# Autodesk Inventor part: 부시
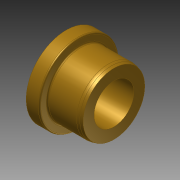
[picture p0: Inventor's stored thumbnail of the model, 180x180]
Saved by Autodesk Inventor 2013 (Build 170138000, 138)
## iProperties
Created: 2016-05
Part Number: 부시
Document SubType Name: Modeling
Designer: mduedu
Density: 7.86 g/cm^3
Material: 강철, 연강
Author: mduedu
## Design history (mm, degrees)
sketch "스케치1"
  geometry: L1 (0, 0)-(18, 0); L2 (1.5, 7.5)-(18, 7.5); L3 (18, 7.5)-(18, 11.598); L4 (16.5, 12)-(5, 12); L5 (5, 12)-(5, 15); L6 (5, 15)-(0, 15); L7 (0, 15)-(0, 7.902); L8 (0, 7.902)-(1.5, 7.5); L9 (16.5, 12)-(18, 11.598)
  constraints: 18 end point, 4 parallel, 1 horizontal, 1 perpendicular, 1 point on line, 1 vertical, 1 vertical alignment
  dimensions: "d0" = 18 distance of L1.start L1.end; "d1" = 15 diameter of L2 L1; "d2" = 24 diameter of L4 L1; "d3" = 5 distance of L5.end L6.end; "d4" = 30 diameter of L6 L1; "d9" = 15 deg angle of L2 L8; "d10" = 1.5 horizontal distance of L7.end L2.start; "d13" = 15 deg angle of L4 L9; "d14" = 1.5 distance from line of L4.start L3
revolve "회전1" sketch "스케치1" stored, may be unused: angle "d5" = 90 deg
fillet "모깎기1" dims "d11" = 4
fillet "모깎기2" dims "d12" = 0.5
node "솔리드1"
